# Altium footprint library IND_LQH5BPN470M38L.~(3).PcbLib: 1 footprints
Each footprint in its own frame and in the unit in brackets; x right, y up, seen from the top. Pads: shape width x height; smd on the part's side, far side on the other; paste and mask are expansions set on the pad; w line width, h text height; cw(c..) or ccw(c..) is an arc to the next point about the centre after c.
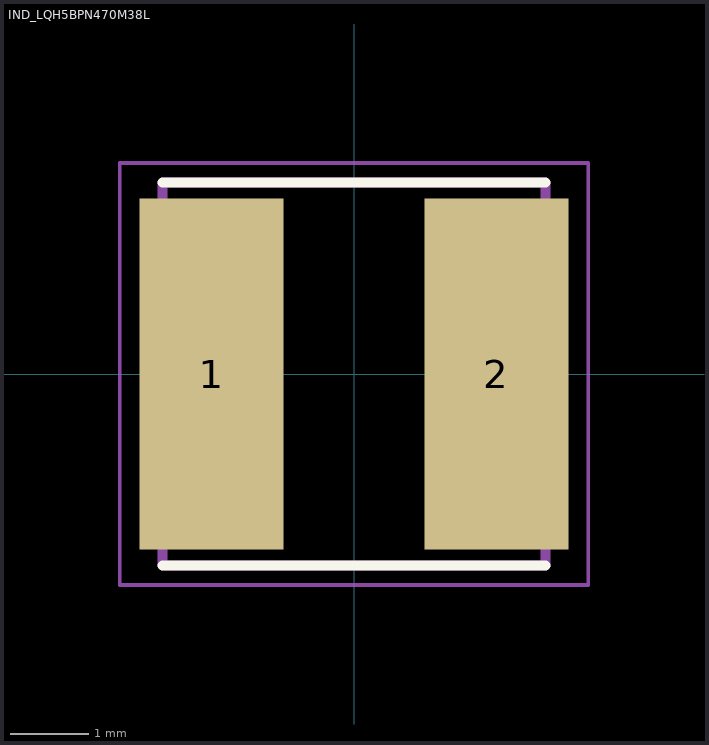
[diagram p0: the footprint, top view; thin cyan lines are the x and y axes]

## IND_LQH5BPN470M38L [mm]
pads (2):
  rect 1.85x4.5 smd: 1(-1.825,0) 2(1.825,0)
Top Overlay:
  lines w0.127: -2.45,-2.45 2.45,-2.45 ; -2.45,2.45 2.45,2.45
Mechanical 13:
  lines w0.127: -2.45,-2.45 2.45,-2.45 2.45,2.45 -2.45,2.45 -2.45,-2.45
Mechanical 15:
  lines w0.05: -3,-2.7 3,-2.7 3,2.7 -3,2.7 -3,-2.7
3D body "IndLQS_2010.stp": height 1.01, standoff 0.01, extent -0.978,-0.886 1.022,0.738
